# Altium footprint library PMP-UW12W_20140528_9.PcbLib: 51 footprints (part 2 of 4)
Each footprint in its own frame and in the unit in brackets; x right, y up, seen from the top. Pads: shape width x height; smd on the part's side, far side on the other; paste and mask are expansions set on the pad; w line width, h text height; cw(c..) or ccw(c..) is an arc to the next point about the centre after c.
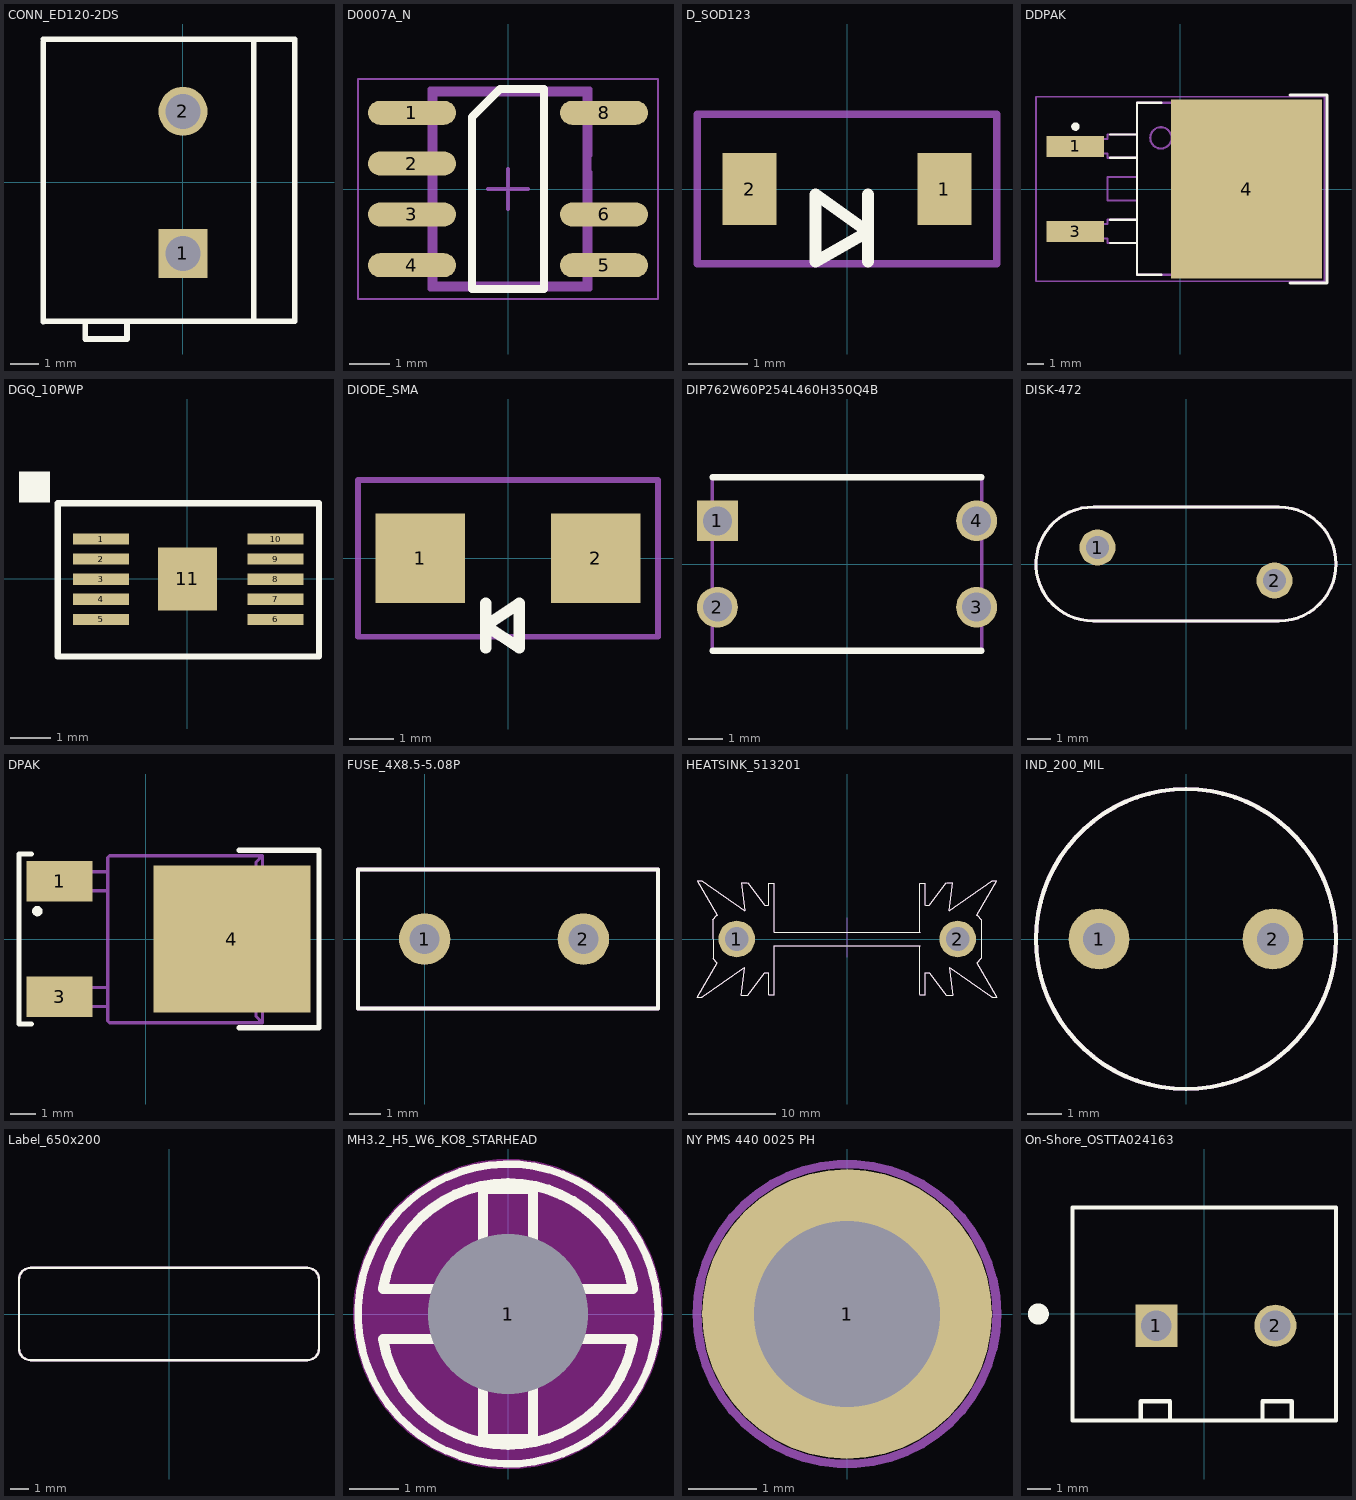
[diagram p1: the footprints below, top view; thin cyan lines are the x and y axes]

## CONN_ED120-2DS [mm] "ONSHORE"
height 13
pads (2):
  rect 1.75x1.75 hole 1.25: 1(0,-2.54)
  round 1.75 hole 1.25: 2(0,2.54)
Top Overlay:
  lines w0.2: -5,-4.985 -5,5.015 ; -5,-4.96 4,-4.96 ; -5,5.115 4,5.115 4,-4.885 ; -3.5,-4.96 -3.5,-5.6 -2,-5.6 -2,-4.96 ; 2.525,-4.95 2.525,5.05
Mechanical 5:
  lines w0.1: -5,-4.96 4,-4.96 ; -5,-4.885 -5,5.115 4,5.115 4,-4.885 ; -3.5,-4.96 -3.5,-5.6 -2,-5.6 -2,-4.96 ; 2.525,-4.875 2.525,5.125
  text ".Designator" at -2.75,-0.4 h1.02
3D body: height 13, standoff 0, extent -5,-4.985 4,5.115
3D body: height 13.1, standoff -2.5, extent -0.496,-3.039 0.5,-2.041
3D body: height 13.1, standoff -2.5, extent -0.496,2.041 0.5,3.039
3D body: height 5.7, standoff 4.3, extent -0.85,1.846 4.15,3.24
3D body: height 5.7, standoff 4.3, extent -0.875,-3.204 4.125,-1.81
3D body: height 13, standoff 0, extent -3.5,-5.6 -2,-4.925

## D0007A_N [mm] "SOIC, 7-Leads, Body 4.9x3.9mm, Pitch 1.27mm, IPC Medium Density"
height 1.75
pads (7):
  oval 2.2x0.6 smd: 1(-2.4,1.905) 2(-2.4,0.635) 3(-2.4,-0.635) 4(-2.4,-1.905) 5(2.4,-1.905) 6(2.4,-0.635) 8(2.4,1.905)
Top Overlay:
  lines w0.2: -0.9,-2.5 0.9,-2.5 0.9,2.5 -0.2,2.5 -0.9,1.8 -0.9,-2.5
Mechanical 5:
  lines w0.127: -1.95,-2.11 -1.95,-2.5 ; -1.95,-1.7 -1.95,-0.84 ; -1.95,-0.43 -1.95,0.43 ; -1.95,0.84 -1.95,1.7 ; -1.95,2.11 -1.95,2.5 ; 2.05,-2.11 2.05,-2.5 ; 2.05,-1.7 2.05,-0.84 ; 2.05,-0.43 2.05,0.43 2.03,0.43 2.03,0.84 2.05,0.84 2.05,1.7 ; 2.05,2.11 2.05,2.5 ; -2.325,-2.11 -2.39,-2.11 -2.95,-2.11 -2.95,-1.7 -2.39,-1.7 -2.325,-1.7 ; -2.325,-2.11 -2.045,-2.11 -1.931,-2.11 -1.931,-1.7 -2.045,-1.7 -2.325,-1.7 ; -2.325,-2.11 -2.325,-1.7 ; -2.325,-0.84 -2.39,-0.84 -2.95,-0.84 -2.95,-0.43 -2.39,-0.43 -2.325,-0.43 ; -2.325,-0.84 -2.045,-0.84 -1.931,-0.84 -1.931,-0.43 -2.045,-0.43 -2.325,-0.43 ; -2.325,-0.84 -2.325,-0.43 ; -2.325,0.43 -2.325,0.84 ; -2.325,0.43 -2.39,0.43 -2.95,0.43 -2.95,0.84 -2.39,0.84 -2.325,0.84 ; -2.325,0.43 -2.045,0.43 -1.931,0.43 -1.931,0.84 -2.045,0.84 -2.325,0.84 ; -2.325,1.7 -2.39,1.7 -2.95,1.7 -2.95,2.11 -2.39,2.11 -2.325,2.11 ; -2.325,1.7 -2.325,2.11 ; -2.325,1.7 -2.045,1.7 -1.931,1.7 -1.931,2.11 -2.045,2.11 -2.325,2.11 ; -1.95,-2.5 -1.822,-2.372 ; -1.95,-2.5 2.05,-2.5 ; -1.95,2.5 2.05,2.5 ; -1.95,2.5 -1.822,2.372 ; -1.822,-2.372 1.922,-2.372 ; -1.822,-2.372 -1.822,2.372 ; -1.822,2.372 1.922,2.372 ; 1.922,-2.372 2.05,-2.5 ; 1.922,-2.372 1.922,2.372 ; 1.922,2.372 2.05,2.5 ; 2.425,-2.11 2.425,-1.7 ; 2.425,-2.11 2.145,-2.11 2.031,-2.11 2.031,-1.7 2.145,-1.7 2.425,-1.7 ; 2.425,-2.11 2.49,-2.11 3.05,-2.11 3.05,-1.7 2.49,-1.7 2.425,-1.7 ; 2.425,-0.84 2.425,-0.43 ; 2.425,-0.84 2.145,-0.84 2.031,-0.84 2.031,-0.43 2.145,-0.43 2.425,-0.43 ; 2.425,-0.84 2.49,-0.84 3.05,-0.84 3.05,-0.43 2.49,-0.43 2.425,-0.43 ; 2.425,1.7 2.425,2.11 ; 2.425,1.7 2.145,1.7 2.031,1.7 2.031,2.11 2.145,2.11 2.425,2.11 ; 2.425,1.7 2.49,1.7 3.05,1.7 3.05,2.11 2.49,2.11 2.425,2.11
  text ".Designator" at -1.4,-0.4 h0.76
Mechanical 15:
  lines w0.05: -3.75,-2.75 -3.75,2.75 3.75,2.75 3.75,-2.75 -3.75,-2.75
  lines w0.1: -0.5,0 0.5,0 ; 0,-0.5 0,0.5
3D body: height 1.54, standoff -0.01, extent -3,-2.5 3,2.5

## D_SOD123 [mil]
pads (2):
  rect 36x48 smd: 1(65,0) 2(-65,0)
Top Overlay:
  lines w8: 14,-48.5 14,-3.5 ; -21,-48.5 14,-28.5 -21,-3.5 -21,-48.5
Mechanical 5:
  lines w5: 14,-49.5 14,-4.5 ; -100,-50 100,-50 100,50 -100,50 -100,-50 ; -21,-49.5 14,-29.5 -21,-4.5 -21,-49.5
  text ".Designator" at -65,5 h30

## DDPAK [mil] "D2-PAK, 3-Pads, Body 9.7x10.4mm (max), TO-263AB, using Vishay Silionix recommended pad sizes"
height 190
pads (3):
  rect 135x49.49 smd: 1(-246.06,100) 3(-246.06,-100)
  rect 355x420 smd paste-181.1: 4(155.51,0)
Top Overlay:
  circle w9.84: c-246.06,146.4 r4.92
  lines w5: -164.37,-126.77 -101.38,-126.77 ; -164.37,-72.05 -101.38,-72.05 ; -164.37,73.23 -101.38,73.23 ; -164.37,127.95 -101.38,127.95 ; -101.38,202.95 -101.38,202.56 ; -44.29,-201.77 -101.38,-201.77 -101.38,-201.38 ; -44.29,-201.38 -101.38,-201.38 ; -44.29,202.56 -101.38,202.56 ; -101.38,-201.38 -101.38,202.56
  lines w7: 258.09,-220.47 344,-220.47 344,220.47 258.09,220.47
Top Paste:
  rectangle: -17.72,147.44 30.28,206.26
  rectangle: 42.09,147.44 90.08,206.26
  rectangle: 101.89,147.44 149.88,206.26
  rectangle: 161.69,147.44 209.69,206.26
  rectangle: 221.5,147.44 269.49,206.26
  rectangle: 281.3,147.44 329.29,206.26
  rectangle: -17.72,76.81 30.28,135.63
  rectangle: 42.09,76.81 90.08,135.63
  rectangle: 101.89,76.81 149.88,135.63
  rectangle: 161.69,76.81 209.69,135.63
  rectangle: 221.5,76.81 269.49,135.63
  rectangle: 281.3,76.81 329.29,135.63
  rectangle: -17.72,6.18 30.28,65
  rectangle: 42.09,6.18 90.08,65
  rectangle: 101.89,6.18 149.88,65
  rectangle: 161.69,6.18 209.69,65
  rectangle: 221.5,6.18 269.49,65
  rectangle: 281.3,6.18 329.29,65
  rectangle: -17.72,-64.45 30.28,-5.63
  rectangle: 42.09,-64.45 90.08,-5.63
  rectangle: 101.89,-64.45 149.88,-5.63
  rectangle: 161.69,-64.45 209.69,-5.63
  rectangle: 221.5,-64.45 269.49,-5.63
  rectangle: 281.3,-64.45 329.29,-5.63
  rectangle: -17.72,-135.08 30.28,-76.26
  rectangle: 42.09,-135.08 90.08,-76.26
  rectangle: 101.89,-135.08 149.88,-76.26
  rectangle: 161.69,-135.08 209.69,-76.26
  rectangle: 221.5,-135.08 269.49,-76.26
  rectangle: 281.3,-135.08 329.29,-76.26
  rectangle: 281.3,-205.71 329.29,-146.89
  rectangle: 221.5,-205.71 269.49,-146.89
  rectangle: 161.69,-205.71 209.69,-146.89
  rectangle: 101.89,-205.71 149.88,-146.89
  rectangle: 42.09,-205.71 90.08,-146.89
  rectangle: -17.72,-205.71 30.28,-146.89
Mechanical 5:
  lines w5: -101.38,-126.77 -171.06,-126.77 -171.06,-116.34 -183.27,-116.34 -223.81,-116.34 ; -101.38,-72.05 -171.06,-72.05 -171.06,-82.48 -183.27,-82.48 -223.81,-82.48 ; -101.38,-26.77 -171.06,-26.77 -171.06,27.95 -101.38,27.95 ; -101.38,73.23 -171.06,73.23 -171.06,83.66 -183.27,83.66 -223.81,83.66 ; -101.38,127.95 -171.06,127.95 -171.06,117.52 -183.27,117.52 -223.81,117.52 ; 268.43,-201.38 306.93,-201.38 323.43,-156.89 323.43,158.07 306.93,202.56 268.43,202.56 ; -223.81,-116.34 -246.26,-116.34 -296.26,-116.34 -296.26,-82.48 -246.26,-82.48 -223.81,-82.48 ; -223.81,-116.34 -223.81,-82.48 ; -223.81,83.66 -223.81,117.52 ; -223.81,83.66 -246.26,83.66 -296.26,83.66 -296.26,117.52 -246.26,117.52 -223.81,117.52 ; -101.38,-201.38 239.17,-201.38 ; -101.38,-201.38 -101.38,202.56 ; -101.38,-201.38 -101.38,-201.77 268.43,-201.77 ; -101.38,202.56 -101.38,202.95 268.43,202.95 ; -101.38,202.56 239.17,202.56 ; 239.17,-201.38 239.17,202.56 ; 239.17,-201.38 268.43,-201.77 ; 239.17,202.56 268.43,202.95 ; 268.43,-201.77 268.43,202.95 ; -70.58,119.94 cw(c-45.58,119.94) -20.58,119.94 cw(c-45.58,119.94) -70.58,119.94
  text ".Designator" at -60,-20 h40
Mechanical 15:
  lines w3.94: -19.69,0 19.68,0 ; 0,-19.68 0,19.68 ; -338.58,-216.54 338.58,-216.54 338.58,216.54 -338.58,216.54 -338.58,-216.54
3D body: height 180.31, standoff 0, extent -295.27,-202.36 324.41,202.36

## DGQ_10PWP [mil]
pads (11):
  rect 55x11 smd: 1(-84.5,39) 2(-84.5,19.3) 3(-84.5,-0.4) 4(-84.5,-20.1) 5(-84.5,-39.8) 6(86.5,-39.8) 7(86.5,-20.1) 8(86.5,-0.4) 9(86.5,19.3) 10(86.5,39)
  rect 57.87x61.81 smd: 11(0,0)
Top Overlay:
  region: -165,75 -135,75 -135,105 -165,105
  lines w6: -127,-76 -127,-61 -127,74 -115,74 129,74 129,-76 -127,-76
Mechanical 5:
  lines w5: -127,-76 -127,74 128.9,74 128.9,-76 -127,-76
  text ".Designator" at 27.5,-115.8 h60
  text "*" at -153.5,55.2 h60

## DIODE_SMA [mil]
pads (2):
  rect 80x80 smd: 1(-78.5,0) 2(78.5,0)
Top Overlay:
  lines w10.1: -20,-80 -20,-40 ; -20,-60 10,-40 10,-80 -20,-60
Mechanical 5:
  lines w5: -20,-80 -20,-40 ; -134,-70 134,-70 134,70 -134,70 -134,-70 ; -20,-60 10,-40 10,-80 -20,-60
  text ".Designator" at -60,-20 h40

## DIP762W60P254L460H350Q4B [mm] "LITE-ON"
height 4.5
pads (4):
  rect 1.2x1.2 hole 0.85: 1(-3.81,1.27)
  round 1.2 hole 0.85: 2(-3.81,-1.27) 3(3.81,-1.27) 4(3.81,1.27)
Top Overlay:
  lines w0.178: -3.96,-2.55 3.96,-2.55 ; -3.96,2.55 3.96,2.55
Mechanical 5:
  lines w0.1: -3.96,-2.55 3.96,-2.55 3.96,2.55 -3.96,2.55 -3.96,-2.55
  text ".Designator" at -2.159,-0.381 h1.02
3D body: height 4.5, standoff 0, extent -3.959,-2.549 3.959,2.549

## DISK-472 [mil]
pads (2):
  round 60 hole 38: 1(-147.5,27.5) 2(147.5,-27.5)
Top Overlay:
  lines w5: -154.17,95 ccw(c-155,0) -155,-95 155,-95 ccw(c155,0) 155,95 -154.1,95
Mechanical 5:
  lines w5: -154.17,95 ccw(c-155,0) -155,-95 155,-95 ccw(c155,0) 155,95 -154.1,95
  text ".Designator" at 295,-35 h60

## DPAK [mm] "D-PAK, 3-Pads, Body 6.22x6.73mm (max), TO-252AA using nominal STEP model"
height 2.39
pads (3):
  rect 2.6x1.6 smd: 1(-3.4,2.28) 3(-3.4,-2.28)
  rect 6.2x5.8 smd paste-2.9: 4(3.4,0)
Top Overlay:
  circle w0.254: c-4.277,1.1 r0.077
  lines w0.2: -4.502,-3.354 -5,-3.354 -5,3.346 -4.502,3.346 ; 3.688,-3.5 6.834,-3.5 6.834,3.5 3.688,3.5
Top Paste:
  rectangle: 0.4,1.625 1.675,2.8
  rectangle: 1.975,1.625 3.25,2.8
  rectangle: 3.55,1.625 4.825,2.8
  rectangle: 5.125,1.625 6.4,2.8
  rectangle: 0.4,0.15 1.675,1.325
  rectangle: 1.975,0.15 3.25,1.325
  rectangle: 3.55,0.15 4.825,1.325
  rectangle: 5.125,0.15 6.4,1.325
  rectangle: 0.4,-1.325 1.675,-0.15
  rectangle: 1.975,-1.325 3.25,-0.15
  rectangle: 3.55,-1.325 4.825,-0.15
  rectangle: 5.125,-1.325 6.4,-0.15
  rectangle: 5.125,-2.8 6.4,-1.625
  rectangle: 3.55,-2.8 4.825,-1.625
  rectangle: 1.975,-2.8 3.25,-1.625
  rectangle: 0.4,-2.8 1.675,-1.625
Mechanical 5:
  lines w0.127: -1.5,1.9 -2.757,1.9 -3.157,1.9 ; -1.5,2.65 -2.757,2.65 -3.157,2.65 ; -3.899,-2.665 -3.357,-2.665 ; -3.899,-2.665 -3.899,-1.915 ; -3.899,-2.665 -3.357,-2.665 ; -3.899,-2.665 -3.899,-1.915 ; -3.899,-2.665 -3.357,-2.665 ; -3.899,-2.665 -3.899,-1.915 ; -3.899,-1.915 -3.357,-1.915 ; -3.899,-1.915 -3.357,-1.915 ; -3.899,-1.915 -3.357,-1.915 ; -3.357,-2.665 -3.157,-2.665 ; -3.357,-2.665 -3.157,-2.665 ; -3.357,-2.665 -3.157,-2.665 ; -3.357,-1.915 -3.157,-1.915 ; -3.357,-1.915 -3.157,-1.915 ; -3.357,-1.915 -3.157,-1.915 ; -3.157,-2.665 -3.157,-1.915 ; -3.157,-2.665 -2.757,-2.665 ; -3.157,-2.665 -3.157,-1.915 ; -3.157,-2.665 -2.757,-2.665 ; -3.157,-2.665 -3.157,-1.915 ; -3.157,-2.665 -2.757,-2.665 ; -3.157,-1.915 -2.757,-1.915 ; -3.157,-1.915 -2.757,-1.915 ; -3.157,-1.915 -2.757,-1.915 ; -3.157,1.9 -3.357,1.9 -3.899,1.9 -3.899,2.65 -3.357,2.65 -3.157,2.65 ; -3.157,1.9 -3.157,2.65 ; -2.757,-2.665 -1.5,-2.665 ; -2.757,-2.665 -1.5,-2.665 ; -2.757,-2.665 -1.5,-2.665 ; -2.757,-1.915 -1.5,-1.915 ; -2.757,-1.915 -1.5,-1.915 ; -2.757,-1.915 -1.5,-1.915 ; -1.5,-2.665 -1.5,-1.915 ; -1.5,-2.665 -1.5,-1.915 ; -1.5,-2.665 -1.5,-1.915 ; -1.5,-2.665 -1.5,-3.157 -1.5,-3.229 -1.429,-3.3 4.6,-3.3 ; -1.5,-1.915 -1.5,3.137 -1.5,3.209 -1.429,3.28 4.6,3.28 ; 4.6,-3.3 4.6,-2.69 5.8,-2.69 5.8,-2.01 5.308,-2.01 5.308,1.99 5.8,1.99 5.8,2.67 4.6,2.67 4.6,3.28 ; 4.6,-3.3 4.348,-3.048 4.348,3.028 4.6,3.28
  text ".Designator" at -0.374,-0.508 h1.02
3D body: height 2.48, standoff 0.01, extent -3.856,-3.29 5.843,3.29

## FUSE_4X8.5-5.08P [mil]
pads (2):
  round 65 / inner rect 65x65 / far side rect 65x65 hole 38: 1(0,0) 2(200,0)
Top Overlay:
  lines w5: -84.03,-87.4 -84.03,87.6 ; -83.88,-87.3 294.07,-87.3 ; -83.88,87.5 294.07,87.5 ; -47.42,87.6 257.46,87.5 ; 294.09,-87.4 294.09,87.6
Mechanical 5:
  lines w5: -84.01,-87.5 -84.01,87.5 ; -83.86,-87.4 294.09,-87.4 ; -83.86,87.4 294.09,87.4 ; -47.4,87.5 257.48,87.4 ; 294.11,-87.5 294.11,87.5
  text ".Designator" at 120,-120 h60

## HEATSINK_513201 [mil]
pads (2):
  round 166 hole 106.5: 1(-500,0) 2(500,0)
Top Overlay:
  lines w5: -680,-263 -589,-108 ; -679,-264 -657,-264 ; -659,-264 -463,-129 ; -608,-87 -591,-107 ; -608,86 -607,-88 ; -608,87 -591,107 ; -589,108 -680,263 -659,264 -463,129 ; -463,-130 -479,-254 -452,-254 ; -463,130 -479,254 -452,254 ; -451,-254 -373,-152 -358,-152 ; -451,254 -373,152 -358,152 ; -356,-152 -356,-252 -331,-252 ; -356,152 -356,252 -331,252 ; -330,-250 -330,-31 330,-31 ; -330,250 -330,31 330,31 ; 328,-250 328,-31 ; 328,31 328,250 ; 329,-252 354,-252 354,-152 ; 329,252 354,252 354,152 ; 356,-152 371,-152 449,-254 ; 356,152 371,152 449,254 ; 450,-254 477,-254 461,-130 ; 450,254 477,254 461,130 ; 461,-129 657,-264 ; 461,129 657,264 ; 587,-108 678,-263 ; 587,108 678,263 ; 589,-107 606,-87 ; 589,107 606,87 607,-87 ; 655,-264 677,-264 ; 655,264 677,264
Mechanical 5:
  lines w5: -680,-263 -589,-108 ; -679,-264 -657,-264 ; -659,-264 -463,-129 ; -608,-87 -591,-107 ; -608,86 -607,-88 ; -608,87 -591,107 ; -589,108 -680,263 -659,264 -463,129 ; -463,-130 -479,-254 -452,-254 ; -463,130 -479,254 -452,254 ; -451,-254 -373,-152 -358,-152 ; -451,254 -373,152 -358,152 ; -356,-152 -356,-252 -331,-252 ; -356,152 -356,252 -331,252 ; -330,-250 -330,-31 330,-31 ; -330,250 -330,31 330,31 ; 1,-82 1,96 ; 328,-250 328,-31 ; 328,31 328,250 ; 329,-252 354,-252 354,-152 ; 329,252 354,252 354,152 ; 356,-152 371,-152 449,-254 ; 356,152 371,152 449,254 ; 450,-254 477,-254 461,-130 ; 450,254 477,254 461,130 ; 461,-129 657,-264 ; 461,129 657,264 ; 587,-108 678,-263 ; 587,108 678,263 ; 589,-107 606,-87 ; 589,107 606,87 607,-87 ; 655,-264 677,-264 ; 655,264 677,264
  text ".Designator" at 37,-20 h40
  text "mtg hole" at -116,123 h30

## IND_200_MIL [mil]
pads (2):
  round 70 hole 37: 1(-100,0) 2(100,0)
Top Overlay:
  circle w5: c0,0 r172.5
Mechanical 5:
  circle w5: c0,0 r172.5
  text ".Designator" at -35,205 h40

## Label_650x200 [mil] "Thermal Transfer Label"
height 1
pads (1):
  round 1 on Mech13: 0(0,0)
Top Overlay:
  lines w5: -325,-75 ccw(c-300,-75) -300,-100 300,-100 ccw(c300,-75) 325,-75 325,75 ccw(c300,75) 300,100 -300,100 ccw(c-300,75) -325,75 -325,-75
Mechanical 5:
  lines w5: -325,-75 ccw(c-300,-75) -300,-100 300,-100 ccw(c300,-75) 325,-75 325,75 ccw(c300,75) 300,100 -300,100 ccw(c-300,75) -325,75 -325,-75
  text ".Designator" at -60,-20 h40
3D body: height 1, standoff 0, extent -325.51,-100.51 325.51,100.51

## MH3.2_H5_W6_KO8_STARHEAD [mil]
height 80
pads (1):
  round 20 / inner round 142 / far side round 20 hole 128 unplated mask+64: 1(0,0)
Top Overlay:
  circle w6: c0,0 r120
  lines w8: -100,-20 -20,-20 -20,-100 20,-100 20,-20 100,-20 ; -100.02,-19.91 ccw(c0,-3.35) 99.99,-20.08 ; -100,20 -20,20 -20,100 20,100 20,20 100,20 ; -99.99,20.09 cw(c0,3.36) 100.02,19.92
Keep-Out Layer:
  circle w100: c0,0 r74

## NY PMS 440 0025 PH [mm] "4-40 nylon screw and mounting hole"
height 1.905
pads (1):
  round 4.216 hole 2.705: 1(0,0)
Mechanical 5:
  circle w0.127: c0,0 r2.184
  text ".Designator" at -1.524,-0.508 h1.02
3D body: height 2.69, standoff -8.74, extent -3.302,-3.3 3.296,3.3

## On-Shore_OSTTA024163 [mm] "TERM BLOCK 2x1, 5.08mm, TH"
height 13
pads (2):
  rect 1.8x1.8 hole 1.3: 1(-2.04,-0.5)
  round 1.8 hole 1.3 paste+0: 2(3.04,-0.5)
Top Overlay:
  circle w0.7: c-7.085,0 r0.1
  lines w0.178: -2.713,-4.55 -2.713,-3.726 -1.463,-3.726 -1.463,-4.55 ; 2.487,-4.55 2.487,-3.726 3.737,-3.726 3.737,-4.55 ; -5.63,-4.55 5.63,-4.55 5.63,4.55 -5.63,4.55 -5.63,-4.55
Mechanical 5:
  rectangle: -2.75,-1.341 -1.29,0.25
  lines w0.1: -2.713,-4.551 -2.713,-3.726 -1.463,-3.726 -1.463,-4.55 ; 2.487,-4.551 2.487,-3.726 3.737,-3.726 3.737,-4.55 ; -5.63,-4.55 -5.63,4.55 5.63,4.55 5.63,-4.55 -5.63,-4.55
  text ".Designator" at -0.75,0 h1.02
3D body: height 13, standoff 0, extent -5.68,-4.601 5.68,4.6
